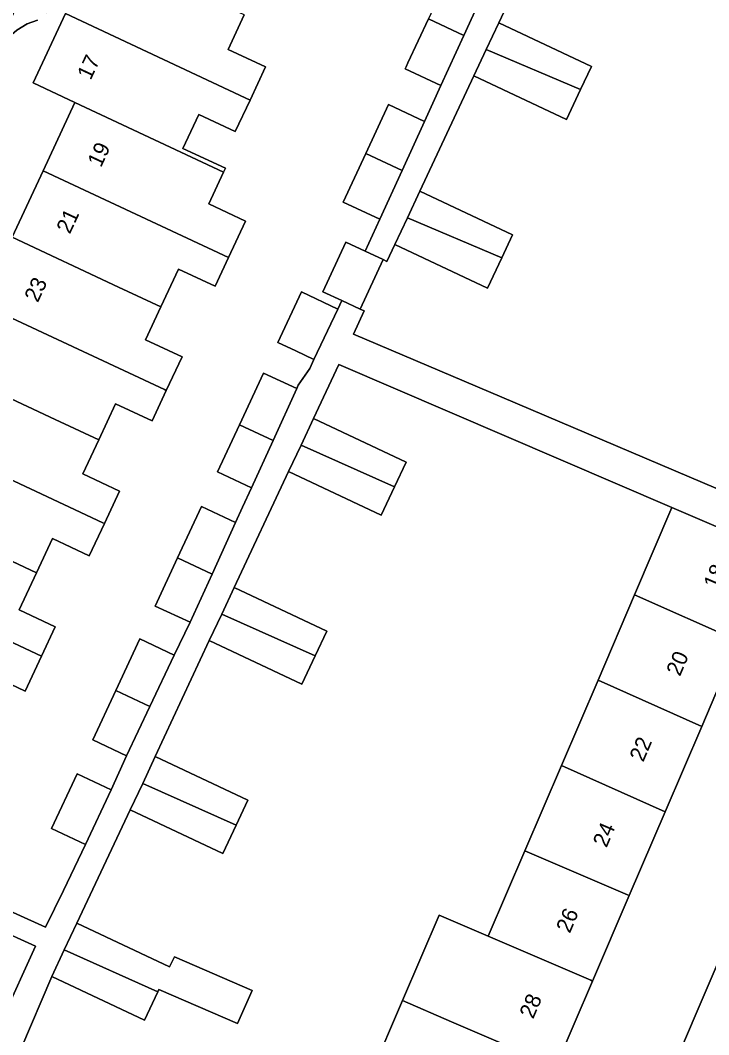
# Model space of a CAD drawing. Extents: x 159817 to 160765, y 380688 to 381638.
# Drawn here: x 160241.3 to 160285.3, y 381356.1 to 381420.9 of the extents above; entities that cross this region are included whole.
import ezdxf

# ---------------------------------------------------------------- set-up
doc = ezdxf.new("R2010")
doc.units = 0
for name, color, linetype in [('IMGEO_Erf', 7, 'Continuous'), ('IMGEO_Pand', 7, 'Continuous'), ('IMGEO_Pand_nummerreeks', 7, 'Continuous'), ('IMGEO_Parkeervlak_open', 7, 'Continuous'), ('IMGEO_Voetpad_halfverhard', 7, 'Continuous'), ('IMGEO_Voetpad_open', 7, 'Continuous')]:
    doc.layers.add(name, color=color, linetype=linetype)

msp = doc.modelspace()

# ---------------------------------------------------------------- linework, layer by layer
at = {"layer": 'IMGEO_Erf'}
for points in [[(160286.28, 381436.572), (160280.568, 381439.245), (160276.92, 381431.45), (160282.844, 381428.659), (160282.151, 381427.188), (160281.243, 381425.263), (160275.32, 381428.054), (160271.868, 381420.701), (160277.791, 381417.91), (160277.098, 381416.439), (160276.19, 381414.514), (160270.267, 381417.305), (160266.832, 381409.94), (160272.755, 381407.149), (160272.062, 381405.678), (160271.155, 381403.753), (160265.231, 381406.544), (160264.72, 381405.46), (160264.473, 381405.575), (160263.003, 381402.416), (160263.263, 381402.295), (160262.575, 381400.815), (160272.062, 381396.784), (160296.864, 381386.245)], [(160233.937, 381366.978), (160242.892, 381362.918), (160244.042, 381365.269), (160245.441, 381368.216), (160243.283, 381369.225), (160244.915, 381372.73), (160247.093, 381371.697), (160248.071, 381373.883), (160245.926, 381374.901), (160247.389, 381378.042), (160248.93, 381381.351), (160251.122, 381380.311), (160252.133, 381382.404), (160249.896, 381383.426), (160251.336, 381386.518), (160252.864, 381389.799), (160255.045, 381388.778), (160255.489, 381389.751), (160256.059, 381390.998), (160253.894, 381392.011), (160255.294, 381395.017), (160256.831, 381398.319), (160258.959, 381397.346), (160259.051, 381397.547), (160259.789, 381398.625), (160260.056, 381399.192), (160258.886, 381399.742), (160257.744, 381400.279), (160259.247, 381403.507), (160261.572, 381402.413), (160261.828, 381402.963), (160260.619, 381403.525), (160262.09, 381406.684), (160263.337, 381406.104), (160264.274, 381408.156), (160261.914, 381409.234), (160263.366, 381412.353), (160264.819, 381415.472), (160267.125, 381414.397), (160267.663, 381415.576), (160268.173, 381416.692), (160265.883, 381417.759), (160265.942, 381417.885), (160266.061, 381418.141), (160267.369, 381420.949)], [(160255.594, 381421.201), (160254.566, 381419.005), (160256.959, 381417.885), (160255.966, 381415.762), (160255.025, 381413.751), (160252.687, 381414.845), (160251.672, 381412.676), (160254.389, 381411.404), (160254.273, 381411.157), (160253.326, 381409.133), (160255.678, 381408.032), (160254.588, 381405.701), (160253.729, 381403.866), (160251.393, 381404.959), (160250.265, 381402.55), (160249.285, 381400.455), (160251.617, 381399.364), (160250.61, 381397.212), (160249.699, 381395.264), (160247.371, 381396.353), (160246.296, 381394.056), (160245.28, 381391.885), (160247.624, 381390.788), (160246.653, 381388.713), (160245.687, 381386.648), (160243.335, 381387.748), (160242.315, 381385.568), (160241.203, 381383.19), (160243.512, 381382.109), (160242.638, 381380.241), (160241.592, 381378.006), (160239.195, 381379.127)], [(160263.685, 381353.508), (160265.713, 381358.236), (160268.053, 381363.692), (160271.198, 381362.344), (160273.538, 381367.799), (160275.877, 381373.254), (160278.217, 381378.71), (160280.556, 381384.165), (160282.945, 381389.736), (160261.654, 381398.862), (160260.034, 381395.425), (160265.957, 381392.633), (160265.211, 381391.05), (160264.357, 381389.238), (160258.434, 381392.029), (160254.958, 381384.63), (160260.881, 381381.839), (160260.135, 381380.256), (160259.281, 381378.443), (160253.357, 381381.235), (160249.907, 381373.822), (160255.83, 381371.031), (160255.084, 381369.448), (160254.23, 381367.635), (160248.307, 381370.426), (160244.897, 381363.178), (160250.82, 381360.387), (160251.127, 381361.038), (160256.093, 381358.876), (160255.175, 381356.766), (160250.145, 381358.955), (160250.074, 381358.804), (160249.22, 381356.991), (160243.297, 381359.782), (160241.303, 381355.124)]]:
    msp.add_lwpolyline(points, dxfattribs=at)
msp.add_lwpolyline([(160295.966, 381384.153), (160289.614, 381386.877), (160287.184, 381381.211), (160284.845, 381375.755), (160282.505, 381370.299), (160280.207, 381364.941), (160277.867, 381359.485), (160275.528, 381354.03), (160273.188, 381348.574), (160270.849, 381343.119), (160268.51, 381337.664), (160266.17, 381332.208), (160263.83, 381326.752), (160261.491, 381321.297), (160259.151, 381315.841), (160256.764, 381310.274), (160263.116, 381307.549)], close=True, dxfattribs=at)
at = {"layer": 'IMGEO_Pand'}
for points in [[(160255.594, 381421.201), (160252.818, 381422.501), (160246.185, 381425.606), (160244.164, 381421.287), (160255.657, 381415.906), (160255.966, 381415.762), (160256.959, 381417.885), (160254.566, 381419.005)], [(160271.192, 381423.299), (160268.942, 381424.327), (160267.369, 381420.949), (160269.635, 381419.892)], [(160244.774, 381415.604), (160251.543, 381412.435), (160254.273, 381411.157), (160254.389, 381411.404), (160251.672, 381412.676), (160252.687, 381414.845), (160255.025, 381413.751), (160255.966, 381415.762), (160255.657, 381415.906), (160244.164, 381421.287), (160242.092, 381416.859)], [(160269.635, 381419.892), (160267.369, 381420.949), (160266.061, 381418.141), (160265.942, 381417.885), (160265.883, 381417.759), (160268.173, 381416.692)], [(160271.065, 381418.997), (160277.098, 381416.439), (160277.791, 381417.91), (160271.868, 381420.701)], [(160271.065, 381418.997), (160270.267, 381417.305), (160276.19, 381414.514), (160277.098, 381416.439)], [(160242.736, 381411.249), (160254.588, 381405.701), (160255.678, 381408.032), (160253.326, 381409.133), (160254.273, 381411.157), (160251.543, 381412.435), (160244.774, 381415.604)], [(160267.125, 381414.397), (160264.819, 381415.472), (160263.366, 381412.353), (160265.696, 381411.269)], [(160265.696, 381411.269), (160263.366, 381412.353), (160261.914, 381409.234), (160264.274, 381408.156)], [(160242.736, 381411.249), (160240.749, 381407.004), (160247.55, 381403.821), (160250.265, 381402.55), (160251.393, 381404.959), (160253.729, 381403.866), (160254.588, 381405.701)], [(160272.062, 381405.678), (160272.755, 381407.149), (160266.832, 381409.94), (160266.029, 381408.236)], [(160272.062, 381405.678), (160266.029, 381408.236), (160265.231, 381406.544), (160271.155, 381403.753)], [(160250.61, 381397.212), (160251.617, 381399.364), (160249.285, 381400.455), (160250.265, 381402.55), (160247.55, 381403.821), (160240.749, 381407.004), (160238.763, 381402.758), (160250.491, 381397.268)], [(160264.473, 381405.575), (160263.337, 381406.104), (160262.09, 381406.684), (160260.619, 381403.525), (160261.828, 381402.963), (160263.003, 381402.416)], [(160261.572, 381402.413), (160259.247, 381403.507), (160257.744, 381400.279), (160258.886, 381399.742), (160260.056, 381399.192)], [(160250.61, 381397.212), (160250.491, 381397.268), (160238.763, 381402.758), (160236.776, 381398.512), (160243.514, 381395.358), (160246.296, 381394.056), (160247.371, 381396.353), (160249.699, 381395.264)], [(160246.296, 381394.056), (160243.514, 381395.358), (160236.776, 381398.512), (160234.789, 381394.267), (160246.548, 381388.762), (160246.653, 381388.713), (160247.624, 381390.788), (160245.28, 381391.885)], [(160258.959, 381397.346), (160256.831, 381398.319), (160255.294, 381395.017), (160257.437, 381394.014)], [(160265.211, 381391.05), (160265.957, 381392.633), (160260.034, 381395.425), (160259.229, 381393.717)], [(160257.437, 381394.014), (160255.294, 381395.017), (160253.894, 381392.011), (160256.059, 381390.998)], [(160242.315, 381385.568), (160243.335, 381387.748), (160245.687, 381386.648), (160246.653, 381388.713), (160246.548, 381388.762), (160234.789, 381394.267), (160232.802, 381390.02), (160239.584, 381386.846)], [(160265.211, 381391.05), (160259.229, 381393.717), (160258.434, 381392.029), (160264.357, 381389.238)], [(160242.315, 381385.568), (160239.584, 381386.846), (160232.802, 381390.02), (160230.816, 381385.775), (160242.638, 381380.241), (160243.512, 381382.109), (160241.203, 381383.19)], [(160255.045, 381388.778), (160252.864, 381389.799), (160251.336, 381386.518), (160253.541, 381385.486)], [(160280.556, 381384.165), (160287.184, 381381.211), (160289.614, 381386.877), (160285.019, 381388.847), (160282.945, 381389.736)], [(160253.541, 381385.486), (160251.336, 381386.518), (160249.896, 381383.426), (160252.133, 381382.404)], [(160230.816, 381385.775), (160228.778, 381381.421), (160235.539, 381378.255), (160237.306, 381377.428), (160238.203, 381377.008), (160239.195, 381379.127), (160241.592, 381378.006), (160242.638, 381380.241)], [(160260.135, 381380.256), (160260.881, 381381.839), (160254.958, 381384.63), (160254.153, 381382.923)], [(160284.845, 381375.755), (160287.184, 381381.211), (160280.556, 381384.165), (160278.217, 381378.71)], [(160260.135, 381380.256), (160254.153, 381382.923), (160253.357, 381381.235), (160259.281, 381378.443)], [(160251.122, 381380.311), (160248.93, 381381.351), (160247.389, 381378.042), (160249.562, 381377.025)], [(160275.877, 381373.254), (160282.505, 381370.299), (160284.845, 381375.755), (160278.217, 381378.71)], [(160249.562, 381377.025), (160247.389, 381378.042), (160245.926, 381374.901), (160248.071, 381373.883)], [(160249.102, 381372.114), (160255.084, 381369.448), (160255.83, 381371.031), (160249.907, 381373.822)], [(160247.093, 381371.697), (160244.915, 381372.73), (160243.283, 381369.225), (160245.441, 381368.216)], [(160275.877, 381373.254), (160273.538, 381367.799), (160280.098, 381364.988), (160280.207, 381364.941), (160282.505, 381370.299)], [(160249.102, 381372.114), (160248.307, 381370.426), (160254.23, 381367.635), (160255.084, 381369.448)], [(160271.198, 381362.344), (160277.758, 381359.532), (160277.867, 381359.485), (160280.207, 381364.941), (160280.098, 381364.988), (160273.538, 381367.799)], [(160277.867, 381359.485), (160277.758, 381359.532), (160271.198, 381362.344), (160268.053, 381363.692), (160265.713, 381358.236), (160268.858, 381356.888), (160275.419, 381354.077), (160275.528, 381354.03)], [(160244.897, 381363.178), (160244.092, 381361.471), (160250.074, 381358.804), (160250.145, 381358.955), (160255.175, 381356.766), (160256.093, 381358.876), (160251.127, 381361.038), (160250.82, 381360.387)], [(160240.135, 381357.076), (160242.241, 381361.71), (160239.61, 381362.906), (160237.517, 381358.299)], [(160250.074, 381358.804), (160244.092, 381361.471), (160243.297, 381359.782), (160249.22, 381356.991)], [(160275.528, 381354.03), (160275.419, 381354.077), (160268.858, 381356.888), (160265.713, 381358.236), (160263.685, 381353.508), (160263.461, 381352.985), (160263.373, 381352.78), (160263.871, 381352.567), (160266.519, 381351.432), (160273.079, 381348.621), (160273.188, 381348.574)]]:
    msp.add_lwpolyline(points, close=True, dxfattribs=at)
at = {"layer": 'IMGEO_Parkeervlak_open'}
msp.add_lwpolyline([(160242.949, 381421.345), (160256.994, 381451.287), (160257.06, 381451.999), (160256.452, 381453.562), (160256.33, 381454.336), (160239.821, 381419.196), (160241.06, 381420.23), (160241.717, 381420.641), (160242.37, 381420.869)], dxfattribs=at)
at = {"layer": 'IMGEO_Voetpad_halfverhard'}
for points in [[(160271.192, 381423.299), (160269.635, 381419.892), (160268.173, 381416.692), (160267.663, 381415.576), (160267.125, 381414.397), (160265.696, 381411.269), (160264.274, 381408.156), (160263.337, 381406.104), (160264.473, 381405.575), (160264.72, 381405.46), (160265.231, 381406.544), (160266.029, 381408.236), (160266.832, 381409.94), (160270.267, 381417.305), (160271.065, 381418.997), (160271.868, 381420.701), (160275.32, 381428.054)], [(160296.864, 381386.245), (160272.062, 381396.784), (160262.575, 381400.815), (160263.263, 381402.295), (160263.003, 381402.416), (160261.828, 381402.963), (160261.572, 381402.413), (160260.056, 381399.192), (160259.789, 381398.625), (160259.051, 381397.547), (160258.959, 381397.346), (160257.437, 381394.014), (160256.059, 381390.998), (160255.489, 381389.751), (160255.045, 381388.778), (160253.541, 381385.486), (160252.133, 381382.404), (160251.122, 381380.311), (160249.562, 381377.025), (160248.071, 381373.883), (160247.093, 381371.697), (160245.441, 381368.216), (160244.042, 381365.269), (160242.892, 381362.918), (160233.937, 381366.978)], [(160239.064, 381350.674), (160241.303, 381355.124), (160243.297, 381359.782), (160244.092, 381361.471), (160244.897, 381363.178), (160248.307, 381370.426), (160249.102, 381372.114), (160249.907, 381373.822), (160253.357, 381381.235), (160254.153, 381382.923), (160254.958, 381384.63), (160258.434, 381392.029), (160259.229, 381393.717), (160260.034, 381395.425), (160261.654, 381398.862), (160282.945, 381389.736), (160285.019, 381388.847), (160289.614, 381386.877)], [(160239.61, 381362.906), (160242.241, 381361.71), (160240.135, 381357.076)]]:
    msp.add_lwpolyline(points, dxfattribs=at)
at = {"layer": 'IMGEO_Voetpad_open'}
for points in [[(160315.157, 381428.903), (160296.864, 381386.245), (160295.966, 381384.153), (160263.116, 381307.549), (160262.44, 381305.973), (160244.191, 381263.419), (160241.628, 381256.815), (160244.429, 381257.572)], [(160225.791, 381377.397), (160227.869, 381381.844), (160228.778, 381381.421), (160230.816, 381385.775), (160232.802, 381390.02), (160234.789, 381394.267), (160236.776, 381398.512), (160238.763, 381402.758), (160240.749, 381407.004), (160242.736, 381411.249), (160244.774, 381415.604), (160242.092, 381416.859), (160244.164, 381421.287)], [(160242.37, 381420.869), (160241.717, 381420.641), (160241.06, 381420.23), (160239.821, 381419.196), (160236.919, 381416.539), (160236.498, 381415.913), (160236.062, 381415.002)]]:
    msp.add_lwpolyline(points, dxfattribs=at)

# ---------------------------------------------------------------- texts
at = {"layer": 'IMGEO_Pand_nummerreeks'}
for s, rotation, p in [('17', 64.92201, (160245.774, 381416.99)), ('19', 64.92258, (160246.433, 381411.411)), ('21', 64.92258, (160244.443, 381407.158)), ('23', 64.92258, (160242.396, 381402.783)), ('18', 66.78868, (160285.836, 381384.461)), ('20', 66.78868, (160283.454, 381378.906)), ('22', 66.78868, (160281.105, 381373.429)), ('24', 66.78868, (160278.759, 381367.96)), ('26', 66.78868, (160276.413, 381362.489)), ('28', 66.78969, (160274.068, 381357.02))]:
    msp.add_text(s, height=1, rotation=rotation, dxfattribs=at).set_placement(p)

doc.saveas('drawing.dxf')
